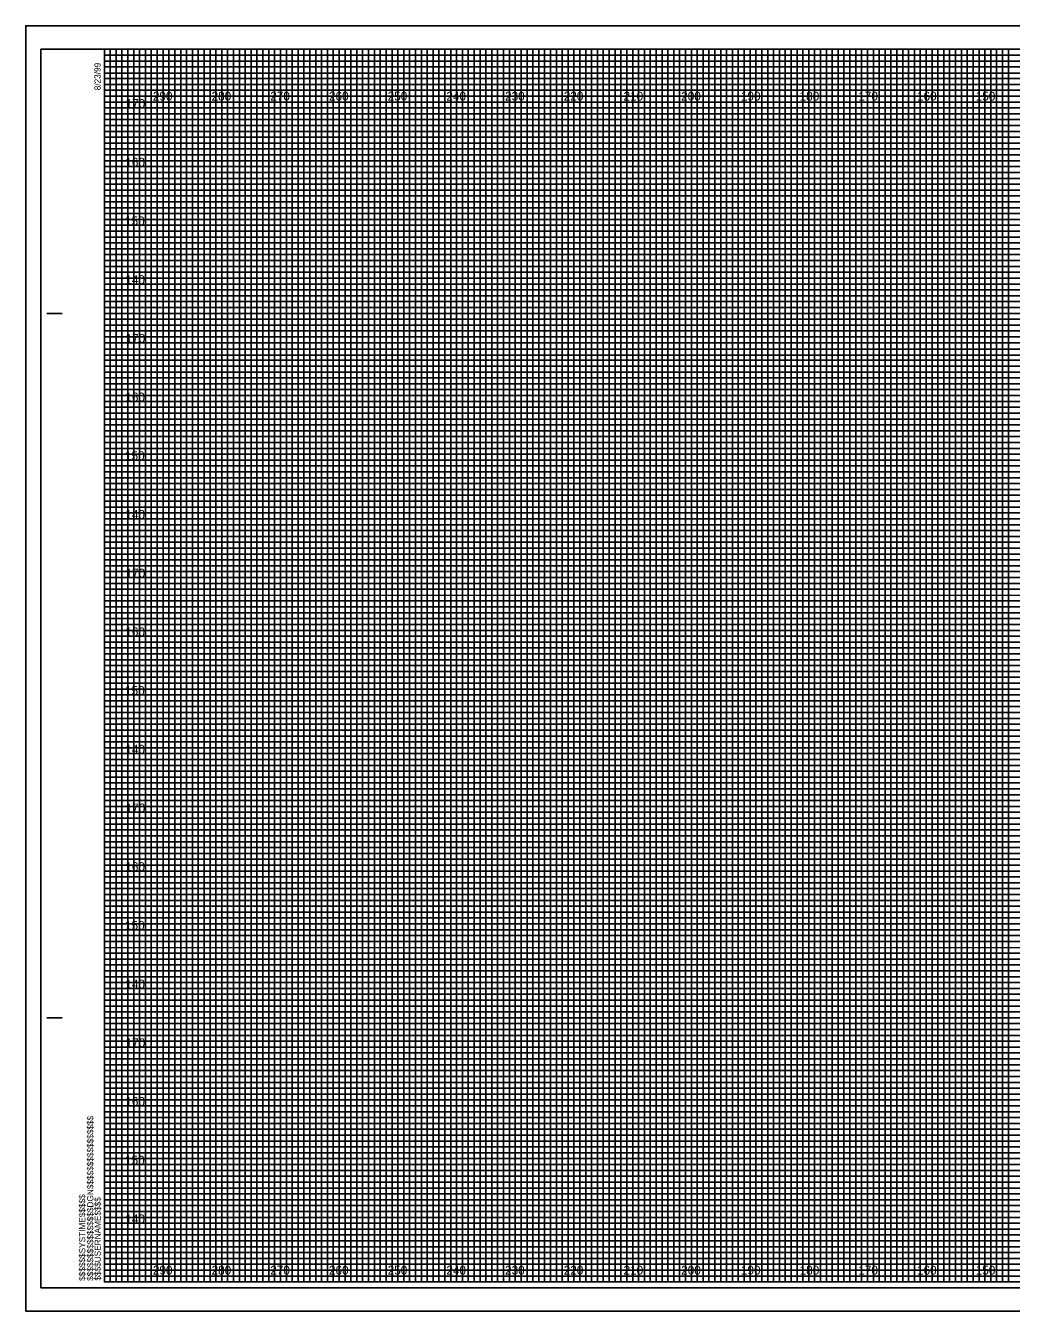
# Model space of a CAD drawing. Extents: x -13 to 323, y -5 to 214.
# Drawn here: x -13.4 to 154.5, y -5 to 214 of the extents above; entities that cross this region are included whole.
import ezdxf

# ---------------------------------------------------------------- set-up
doc = ezdxf.new("R2010")
doc.units = 0
for name, color, linetype in [('Exist Cross Section Cell', 7, 'Continuous'), ('Exist XS Center Line Elevation Label', 7, 'Continuous'), ('Exist XS Ground Line', 7, 'Continuous'), ('Prop CMT Pvmt Course 1', 7, 'Continuous'), ('Prop CMT Pvmt Course 2', 7, 'Continuous'), ('Prop CMT Pvmt Surface', 7, 'Continuous'), ('Prop CMT Pvmt Surface Shoulder', 7, 'Continuous'), ('Prop CMT Shld Paved Course 1', 7, 'Continuous'), ('Prop CMT Shld Paved Course 2', 7, 'Continuous'), ('Prop XS Vertical Lines Alignments', 7, 'Continuous'), ('Scratch_Level_9', 7, 'Continuous')]:
    doc.layers.add(name, color=color, linetype=linetype)

msp = doc.modelspace()

# ---------------------------------------------------------------- linework, layer by layer
at = {"layer": 'Exist XS Center Line Elevation Label'}
for p, q in [((0, 209), (260, 209)), ((260, 207.98), (0, 207.98)), ((0, 207.98), (0, 207)), ((0, 207), (260, 207)), ((260, 205.89), (0, 205.89)), ((0, 205.89), (0, 204)), ((0, 204), (320, 204))]:
    msp.add_line(p, q, dxfattribs=at)
for points in [[(0, 203), (270, 203), (320, 203), (320, 202), (0, 202)], [(0, 201), (320, 201), (320, 199), (0, 199)], [(0, 198), (320, 198), (320, 197), (0, 196.98)], [(0, 196), (320, 196), (320, 194), (0, 194)], [(0, 193), (320, 193), (320, 192), (0, 192)], [(0, 191), (320, 191), (320, 189), (0, 189)], [(0, 188), (320, 188), (320, 187), (0, 187)], [(0, 186), (320, 186), (320, 184), (0, 184)], [(0, 183), (320, 183), (320, 182), (0, 182)], [(0, 181), (320, 181), (320, 179), (0, 179)], [(0, 178), (320, 178), (320, 177), (0, 177)], [(0, 176), (320, 176), (320, 173.95), (320, 173), (320, 172), (0, 172)], [(0, 174), (320, 174), (320, 173), (0, 173)], [(0, 171), (320, 171), (320, 169), (0, 169.03)], [(0, 169.03), (320, 169), (320, 168), (0, 168)], [(0, 167), (320, 167), (320, 166), (0, 166)], [(0, 164), (320, 164), (320, 163), (0, 163)], [(0, 162), (320, 162), (320, 161), (0, 161)], [(-0.07, 158.89), (320, 158.89), (320, 157.88), (-0.07, 157.88)], [(0, 157), (320, 157), (320, 156), (0, 156)], [(0, 154), (320, 154), (320, 153), (0, 153)], [(0, 152), (320, 152), (320, 151), (0, 151)], [(0, 149), (320, 149), (320, 148), (0, 148)], [(0, 147), (320, 147), (320, 146), (0, 146)], [(0, 144), (320, 144), (320, 143), (0, 143)], [(0, 142), (320, 142), (320, 141), (0, 141)], [(0, 139), (320, 139), (319.99, 137.98), (0, 138)], [(0, 137), (320, 137), (320, 136), (0, 136)], [(0, 134), (320, 134), (320, 133), (0, 133)], [(0, 132), (320, 132), (320, 131), (0, 131)], [(0, 129), (320, 129), (320, 128), (0, 128)], [(0, 127), (320, 127), (320, 126), (0, 126)], [(0, 124), (320, 124), (320, 123), (0, 123)], [(0, 122), (320, 122), (320, 121), (0, 121)], [(0, 119), (320, 119), (320, 118), (0, 118)], [(0, 116.99), (320.07, 116.91), (320, 116), (0, 116)], [(0, 114), (320, 114), (320, 113), (0, 113)], [(0, 112), (320, 112), (320, 111), (0, 111)], [(0, 109), (320, 109), (320, 108), (0, 108)], [(0, 107), (320, 107), (320, 106), (0, 106)], [(0, 104), (320, 104), (320, 103), (0, 103)], [(0, 102), (320, 102), (320, 101), (0, 101)], [(0, 99), (320, 99), (320, 98), (0, 98)], [(0, 97), (320, 97), (320, 96), (0, 96)], [(0, 94), (320, 94), (320, 93), (0, 93)], [(0, 92), (320, 92), (320, 91), (0, 91)], [(0, 89), (320, 89), (320, 88), (0, 88)], [(0, 87), (320, 87), (320, 86), (0, 86)], [(0, 84), (320, 84), (320, 83), (0, 83)], [(0, 82), (320, 82), (320, 81), (0, 81)], [(0, 79), (320, 79), (319.99, 77.98), (0, 78)], [(0, 77), (320, 77), (320, 76), (0, 76)], [(0, 74), (320, 74), (320, 73), (0, 73)], [(0, 72), (320, 72), (320, 71), (0, 71)], [(0, 69), (320, 69), (320, 68), (0, 68)], [(0, 67), (320, 67), (320, 66), (0, 66)], [(0, 64), (320, 64), (320, 63), (0, 63)], [(0, 62), (320, 62), (320, 61), (0, 61)], [(0, 59), (320, 59), (320, 58), (0, 58)], [(0, 56.99), (320.07, 56.91), (320, 56), (0, 56)], [(0, 54), (320, 54), (320, 53), (0, 53)], [(0, 52), (320, 52), (320, 51), (0, 51)], [(0, 49), (320, 49), (320, 48), (0, 48)], [(0, 47), (320, 47), (320, 46), (0, 46)], [(0, 44), (320, 44), (320, 43), (0, 43)], [(0, 42), (320, 42), (320, 41), (0, 41)], [(0, 39), (320, 39), (320, 38), (0, 38)], [(0, 37), (320, 37), (320, 36), (0, 36)], [(0, 34), (320, 34), (320, 33), (0, 33)], [(0, 32), (320, 32), (320, 31), (0, 31)], [(0, 29), (320, 29), (320, 28), (0, 28)], [(0, 27), (320, 27), (320, 26), (0, 26)], [(0, 24), (320, 24), (320, 23), (0, 23)], [(0, 22), (320, 22), (320, 21), (0, 21)], [(0, 19), (320, 19), (320, 18), (0, 18)], [(0, 17), (320, 17), (320, 16), (0, 16)], [(0, 14), (320, 14), (320, 13), (0, 13)], [(0, 12), (320, 12), (320, 11), (0, 11)], [(0, 9), (320, 9), (320, 8), (0, 8)], [(0, 7), (320, 7), (320, 6), (0, 6)], [(0, 4), (320, 4), (320, 3), (0, 3)], [(0, 2), (320, 2), (320, 1), (0, 1)]]:
    msp.add_lwpolyline(points, dxfattribs=at)
at = {"layer": 'Exist XS Ground Line'}
for points in [[(0, 210), (5, 210), (5, 0), (15, 0), (15, 210), (25, 210), (25, 0), (35, 0), (35, 210), (45, 210), (45, 0), (55, 0), (55, 210), (65, 210), (65, 0), (75, 0), (75, 210), (85, 210), (85, 0), (95, 0), (95, 210), (105, 210), (105, 0), (115, 0), (115, 210), (125, 210), (125, 0), (135, 0), (135, 210), (145, 210), (145, 0), (155, 0)], [(0, 205), (275, 205)], [(0, 185), (320, 185), (320, 195), (0, 195)], [(0, 165), (320, 165), (320, 175), (0, 175)], [(0, 145), (320, 145), (320, 155), (0, 155)], [(0, 125), (320, 125), (320, 135), (0, 135)], [(0, 105), (320, 105), (320, 115), (0, 115)], [(0, 85), (320, 85), (320, 95), (0, 95)], [(0, 65), (320, 65), (320, 75), (0, 75)], [(0, 45), (320, 45), (320, 55), (0, 55)], [(0, 25), (320, 25), (320, 35), (0, 35)], [(0, 5), (320, 5), (320, 15), (0, 15)]]:
    msp.add_lwpolyline(points, dxfattribs=at)
at = {"layer": 'Prop CMT Pvmt Course 1'}
for p, q in [((323.3, 214), (-13.4, 214)), ((-13.4, 214), (-13.4, -5)), ((-13.4, -5), (323.3, -5))]:
    msp.add_line(p, q, dxfattribs=at)
at = {"layer": 'Prop CMT Pvmt Surface'}
msp.add_lwpolyline([(-13.4, -5), (323.3, -5), (323.3, 214), (-13.4, 214)], close=True, dxfattribs=at)
at = {"layer": 'Prop CMT Pvmt Surface Shoulder'}
for p, q in [((10, 0), (10, 210)), ((20, 0), (20, 210)), ((30, 0), (30, 210)), ((40, 0), (40, 210)), ((50, 0), (50, 210)), ((60, 0), (60, 210)), ((70, 0), (70, 210)), ((80, 0), (80, 210)), ((90, 0), (90, 210)), ((100, 0), (100, 210)), ((110, 0), (110, 210)), ((120, 0), (120, 210)), ((130, 0), (130, 210)), ((140, 0), (140, 210)), ((150, 0), (150, 210)), ((0, 200), (320, 200)), ((0, 190), (320, 190)), ((0, 180), (320, 180)), ((0, 170), (320, 170)), ((0, 160), (320, 160)), ((0, 150), (320, 150)), ((0, 140), (320, 140)), ((0, 130), (320, 130)), ((0, 120), (320, 120)), ((0, 110), (320, 110)), ((0, 100), (320, 100)), ((0, 90), (320, 90)), ((0, 80), (320, 80)), ((0, 70), (320, 70)), ((0, 60), (320, 60)), ((0, 50), (320, 50)), ((0, 40), (320, 40)), ((0, 30), (320, 30)), ((0, 20), (320, 20)), ((0, 10), (320, 10))]:
    msp.add_line(p, q, dxfattribs=at)
at = {"layer": 'Prop CMT Shld Paved Course 1'}
for p, q in [((-9.8, 165), (-7.3, 165)), ((-9.7, 165), (-7.2, 165)), ((-9.8, 45), (-7.3, 45)), ((-9.7, 45), (-7.2, 45)), ((0, 0), (0, 0)), ((0, 0), (0, 0)), ((0, 0), (0, 0)), ((0, 0), (0, 0)), ((0, 0), (0, 0)), ((0, 0), (0, 0)), ((0, 0), (0, 0))]:
    msp.add_line(p, q, dxfattribs=at)
msp.add_lwpolyline([(320, 210), (0, 210), (0, 0), (320, 0)], close=True, dxfattribs=at)
at = {"layer": 'Prop CMT Shld Paved Course 2'}
for points in [[(0, 0), (1, 0), (1, 210), (2, 210), (2, 0)], [(2, 0), (3, 0), (3, 210), (4, 210), (4, 0)], [(5, 0), (6, 0), (6, 210), (7, 210), (7, 0)], [(7, 0), (8, 0), (8, 210), (9, 210), (9, 0)], [(10, 0), (11, 0), (11, 210), (12, 210), (12, 0)], [(12, 0), (13, 0), (13, 210), (14, 210), (14, 0)], [(15, 0), (16, 0), (16, 210), (17, 210), (17, 0)], [(17, 0), (18, 0), (18, 210), (19, 210), (19, 0)], [(20, 0), (21, 0), (21, 210), (22, 210), (22, 0)], [(22, 0), (23, 0), (23, 210), (24, 210), (24, 0)], [(25, 0), (26, 0), (26, 210), (27, 210), (27, 0)], [(27, 0), (28, 0), (28, 210), (29, 210), (29, 0)], [(30, 0), (31, 0), (31, 210), (32, 210), (32, 0)], [(32, 0), (33, 0), (33, 210), (34, 210), (34, 0)], [(35, 0), (36, 0), (36, 210), (37, 210), (37, 0)], [(37, 0), (38, 0), (38, 210), (39, 210), (39, 0)], [(40, 0), (41, 0), (41, 210), (42, 210), (42, 0)], [(42, 0), (43, 0), (43, 210), (44, 210), (44, 0)], [(45, 0), (46, 0), (46, 210), (47, 210), (47, 0)], [(47, 0), (48, 0), (48, 210), (49, 210), (49, 0)], [(50, 0), (51, 0), (51, 210), (52, 210), (52, 0)], [(52, 0), (53, 0), (53, 210), (54, 210), (54, 0)], [(55, 0), (56, 0), (56, 210), (57, 210), (57, 0)], [(57, 0), (58, 0), (58, 210), (59, 210), (59, 0)], [(60, 0), (61, 0), (61, 210), (62, 210), (62, 0)], [(62, 0), (63, 0), (63, 210), (64, 210), (64, 0)], [(65, 0), (66, 0), (66, 210), (67, 210), (67, 0)], [(67, 0), (68, 0), (68, 210), (69, 210), (69, 0)], [(70, 0), (71, 0), (71, 210), (72, 210), (72, 0)], [(72, 0), (73, 0), (73, 210), (74, 210), (74, 0)], [(75, 0), (76, 0), (76, 210), (77, 210), (77, 0)], [(77, 0), (78, 0), (78, 210), (79, 210), (79, 0)], [(80, 0), (81, 0), (81, 210), (82, 210), (82, 0)], [(82, 0), (83, 0), (83, 210), (84, 210), (84, 0)], [(85, 0), (86, 0), (86, 210), (87, 210), (87, 0)], [(87, 0), (88, 0), (88, 210), (89, 210), (89, 0)], [(90, 0), (91, 0), (91, 210), (92, 210), (92, 0)], [(92, 0), (93, 0), (93, 210), (94, 210), (94, 0)], [(95, 0), (96, 0), (96, 210), (97, 210), (97, 0)], [(97, 0), (98, 0), (98, 210), (99, 210), (99, 0)], [(100, 0), (101, 0), (101, 210), (102, 210), (102, 0)], [(102, 0), (103, 0), (103, 210), (104, 210), (104, 0)], [(105, 0), (106, 0), (106, 210), (107, 210), (107, 0)], [(107, 0), (108, 0), (108, 210), (109, 210), (109, 0)], [(110, 0), (111, 0), (111, 210), (112, 210), (112, 0)], [(112, 0), (113, 0), (113, 210), (114, 210), (114, 0)], [(115, 0), (116, 0), (116, 210), (117, 210), (117, 0)], [(117, 0), (118, 0), (118, 210), (119, 210), (119, 0)], [(120, 0), (121, 0), (121, 210), (122, 210), (122, 0)], [(122, 0), (123, 0), (123, 210), (124, 210), (124, 0)], [(125, 0), (126, 0), (126, 210), (127, 210), (127, 0)], [(127, 0), (128, 0), (128, 210), (129, 210), (129, 0)], [(130, 0), (131, 0), (131, 210), (132, 210), (132, 0)], [(132, 0), (133, 0), (133, 210), (134, 210), (134, 0)], [(135, 0), (136, 0), (136, 210), (137, 210), (137, 0)], [(137, 0), (138, 0), (138, 210), (139, 210), (139, 0)], [(140, 0), (141, 0), (141, 210), (142, 210), (142, 0)], [(142, 0), (143, 0), (143, 210), (144, 210), (144, 0)], [(145, 0), (146, 0), (146, 210), (147, 210), (147, 0)], [(147, 0), (148, 0), (148, 210), (149, 210), (149, 0)], [(150, 0), (151, 0), (151, 210), (152, 210), (152, 0)], [(152, 0), (153, 0), (153, 210), (154, 210), (154, 0)]]:
    msp.add_lwpolyline(points, dxfattribs=at)
at = {"layer": 'Prop XS Vertical Lines Alignments'}
msp.add_lwpolyline([(-10.8, -1), (322.4, -1), (322.4, 210), (-10.8, 210)], close=True, dxfattribs=at)
at = {"layer": 'Scratch_Level_9'}
for p, q in [((10, 210), (0, 210)), ((10, 0), (10, 210)), ((30, 210), (20, 210)), ((20, 210), (20, 0)), ((30, 0), (30, 210)), ((50, 210), (40, 210)), ((40, 210), (40, 0)), ((50, 0), (50, 210)), ((70, 210), (60, 210)), ((60, 210), (60, 0)), ((70, 0), (70, 210)), ((90, 210), (80, 210)), ((80, 210), (80, 0)), ((90, 0), (90, 210)), ((110, 210), (100, 210)), ((100, 210), (100, 0)), ((110, 0), (110, 210)), ((130, 210), (120, 210)), ((120, 210), (120, 0)), ((130, 0), (130, 210)), ((150, 210), (140, 210)), ((140, 210), (140, 0)), ((150, 0), (150, 210)), ((20, 0), (10, 0)), ((40, 0), (30, 0)), ((60, 0), (50, 0)), ((80, 0), (70, 0)), ((100, 0), (90, 0)), ((120, 0), (110, 0)), ((140, 0), (130, 0)), ((160, 0), (150, 0))]:
    msp.add_line(p, q, dxfattribs=at)
for points in [[(0, 200), (320, 200), (320, 190), (0, 190)], [(0, 180), (320, 180), (320, 170), (0, 170)], [(0, 160), (320, 160), (320, 150), (0, 150)], [(0, 140), (320, 140), (320, 130), (0, 130)], [(0, 120), (320, 120), (320, 110), (0, 110)], [(0, 100), (320, 100), (320, 90), (0, 90)], [(0, 80), (320, 80), (320, 70), (0, 70)], [(0, 60), (320, 60), (320, 50), (0, 50)], [(0, 40), (320, 40), (320, 30), (0, 30)], [(0, 20), (320, 20), (320, 10), (0, 10)]]:
    msp.add_lwpolyline(points, dxfattribs=at)

# ---------------------------------------------------------------- texts
at = {"layer": 'Exist Cross Section Cell'}
for s, p in [('290', (8.26, 201.25)), ('280', (18.26, 201.25)), ('270', (28.26, 201.25)), ('260', (38.26, 201.25)), ('250', (48.26, 201.25)), ('240', (58.26, 201.25)), ('230', (68.26, 201.25)), ('220', (78.26, 201.25)), ('210', (88.44, 201.25)), ('200', (98.26, 201.25)), ('190', (108.44, 201.25)), ('180', (118.44, 201.25)), ('170', (128.44, 201.25)), ('160', (138.44, 201.25)), ('150', (148.44, 201.25)), ('290', (8.26, 1.25)), ('280', (18.26, 1.25)), ('270', (28.26, 1.25)), ('260', (38.26, 1.25)), ('250', (48.26, 1.25)), ('240', (58.26, 1.25)), ('230', (68.26, 1.25)), ('220', (78.26, 1.25)), ('210', (88.44, 1.25)), ('200', (98.26, 1.25)), ('190', (108.44, 1.25)), ('180', (118.44, 1.25)), ('170', (128.44, 1.25)), ('160', (138.44, 1.25)), ('150', (148.44, 1.25))]:
    msp.add_text(s, height=1.5, dxfattribs=at).set_placement(p)
at = {"layer": 'Prop CMT Pvmt Course 2'}
for s, p in [('170', (3.61, 200)), ('160', (3.57, 190)), ('150', (3.52, 180)), ('140', (3.57, 170)), ('170', (3.61, 160)), ('160', (3.57, 150)), ('150', (3.52, 140)), ('140', (3.57, 130)), ('170', (3.61, 120)), ('160', (3.57, 110)), ('150', (3.52, 100)), ('140', (3.57, 90)), ('170', (3.61, 80)), ('160', (3.57, 70)), ('150', (3.52, 60)), ('140', (3.57, 50)), ('170', (3.61, 40)), ('160', (3.57, 30)), ('150', (3.52, 20)), ('140', (3.57, 10))]:
    msp.add_text(s, height=1.5, dxfattribs=at).set_placement(p)
at = {"layer": 'Prop CMT Shld Paved Course 1'}
for s, p in [('8/23/99', (-0.65, 203)), ('$$$$$$$$$$$$$$$$DGN$$$$$$$$$$$$$$$$', (-1.88, 0.18)), ('$$$$$$SYSTIME$$$$$', (-3.26, 0.18)), ('$$$$USERNAME$$$$', (-0.62, 0.23))]:
    msp.add_text(s, height=1.05, rotation=90, dxfattribs=at).set_placement(p)

doc.saveas('drawing.dxf')
